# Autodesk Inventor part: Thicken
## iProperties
Shininess: 64.0
Length Units: 11269
Angle Units: 11279
Time Units: 11290
Mass Units: 11283
Length Display Precision: 3
Angle Display Precision: 2
Compacted: True
Part Number: Thicken
Document SubType Name: Modeling
Created: 2002-12
Designer: deepak
Density: 0.0
Volumn: 0.0
Area: 0.0
PropertySet Name: Model Information
Control State: 0
Master: False
Checked Out: False
Author: deepak
